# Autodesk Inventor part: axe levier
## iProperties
Created: 2002-03
Part Number: axe levier
Material: Par défaut
Document SubType Name: Modélisation
Designer: BAVERGE
Control State: 0
Master: False
Checked Out: False
Shininess: 41.0
Length Units: 11269
Angle Units: 11279
Time Units: 11290
Mass Units: 11283
Length Display Precision: 3
Angle Display Precision: 2
Density: 0.0
Volumn: 0.0
Area: 0.0
PropertySet Name: Model Information
Author: BAVERGE
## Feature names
1. Révolution1 [Revolution]
